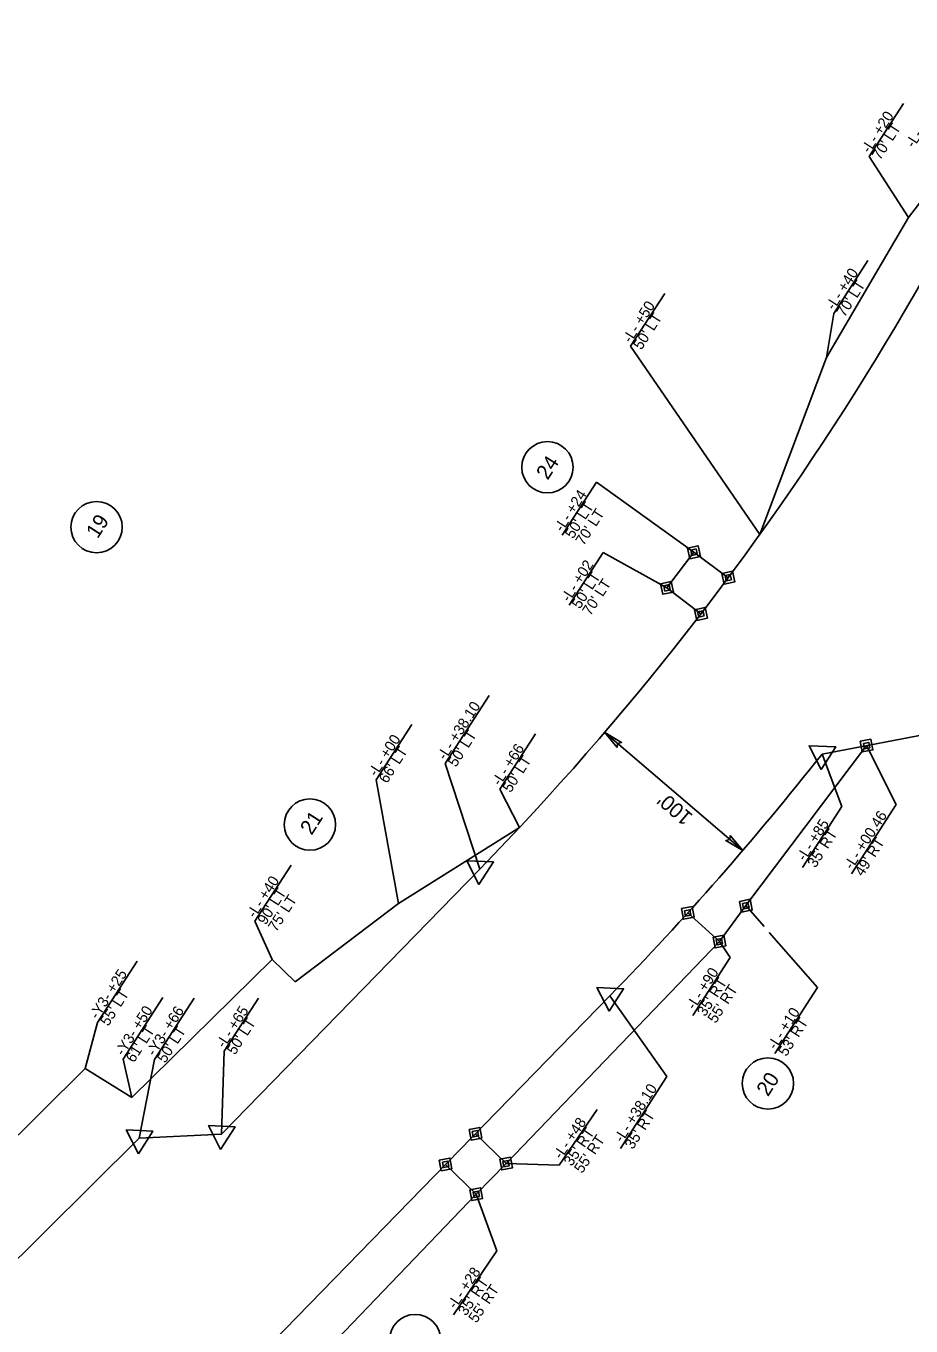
# Model space of a CAD drawing. Extents: x 1975689 to 1978251, y 778490 to 782347.
# Drawn here: x 1976742 to 1977156, y 779960 to 780568 of the extents above; entities that cross this region are included whole.
import ezdxf

# ---------------------------------------------------------------- set-up
doc = ezdxf.new("R2010")
doc.units = 0
for name, color, linetype in [('Prop Easement Aerial Utility', 7, 'Continuous'), ('Prop Easement Aerial Utility Station Offsets', 7, 'Continuous'), ('Prop Easement Construction', 7, 'Continuous'), ('Prop Easement Construction Station Offsets', 7, 'Continuous'), ('Prop Easement Permanent Drainage Utility', 7, 'Continuous'), ('Prop Easement Permanent Drainage Utility Station Offsets', 7, 'Continuous'), ('Prop Easement Permanent Utility', 7, 'Continuous'), ('Prop Parcel Number CELL', 7, 'Continuous'), ('Prop ROW Marker CELL', 7, 'Continuous'), ('Prop ROW Permanent Easement CELL', 7, 'Continuous'), ('Prop ROW RW Lines', 7, 'Continuous'), ('Prop ROW Station Offsets', 7, 'Continuous'), ('Prop ROW Text', 7, 'Continuous'), ('Prop Terminator CELL', 7, 'Continuous')]:
    doc.layers.add(name, color=color, linetype=linetype)

msp = doc.modelspace()

# ---------------------------------------------------------------- linework, layer by layer
at = {"layer": 'Prop Easement Aerial Utility'}
for p, q in [((1977041.51, 780305.06), (1977054.11, 780321.73)), ((1977054.11, 780321.73), (1977070.16, 780309.79)), ((1977041.51, 780305.06), (1977057.36, 780292.87))]:
    msp.add_line(p, q, dxfattribs=at)
at = {"layer": 'Prop Easement Aerial Utility Station Offsets'}
for p, q in [((1976992.52, 780329.72), (1977008.5, 780354.47)), ((1977054.11, 780321.73), (1977008.5, 780354.47)), ((1976995.68, 780296.89), (1977011.66, 780321.64)), ((1977041.51, 780305.06), (1977011.66, 780321.64))]:
    msp.add_line(p, q, dxfattribs=at)
at = {"layer": 'Prop Easement Construction'}
for p, q in [((1977154.47, 780478.39), (1977218.35, 780562.05)), ((1977116.16, 780412.76), (1977154.47, 780478.39)), ((1977084.94, 780330.04), (1977116.16, 780412.76)), ((1976915.88, 780157.37), (1976972.51, 780192.94)), ((1976867.56, 780120.68), (1976915.88, 780157.37)), ((1976791.21, 780066.63), (1976856.81, 780131.15)), ((1976856.81, 780131.15), (1976867.56, 780120.68)), ((1976698.3, 780009.8), (1976769.35, 780080.17)), ((1976769.35, 780080.17), (1976791.21, 780066.63))]:
    msp.add_line(p, q, dxfattribs=at)
at = {"layer": 'Prop Easement Construction Station Offsets'}
for p, q in [((1977136.12, 780506.87), (1977152.1, 780531.62)), ((1977154.47, 780478.39), (1977136.12, 780506.87)), ((1977119.52, 780433.44), (1977135.49, 780458.19)), ((1977024.45, 780418.08), (1977040.43, 780442.83)), ((1977116.16, 780412.76), (1977119.52, 780433.44)), ((1977024.45, 780418.08), (1977084.94, 780330.04)), ((1976905.47, 780215.23), (1976922.17, 780241.09)), ((1976963.31, 780210.92), (1976980, 780236.78)), ((1976915.88, 780157.37), (1976905.47, 780215.23)), ((1976972.51, 780192.94), (1976963.31, 780210.92)), ((1976848.71, 780149.05), (1976865.66, 780175.31)), ((1976856.81, 780131.15), (1976848.71, 780149.05)), ((1976775.11, 780101.69), (1976793.67, 780130.44)), ((1976787.12, 780084.57), (1976805.68, 780113.33)), ((1976769.35, 780080.17), (1976775.11, 780101.69)), ((1976791.21, 780066.63), (1976787.12, 780084.57))]:
    msp.add_line(p, q, dxfattribs=at)
at = {"layer": 'Prop Easement Permanent Drainage Utility'}
for p, q in [((1977078.38, 780156.36), (1977134.87, 780231.26)), ((1977066.05, 780139.53), (1977078.38, 780156.36)), ((1977051.22, 780152.94), (1977066.05, 780139.53)), ((1976966.24, 780035.68), (1976951.92, 780049.64)), ((1976952.28, 780021.36), (1976937.96, 780035.32)), ((1976952.28, 780021.36), (1976966.24, 780035.68))]:
    msp.add_line(p, q, dxfattribs=at)
at = {"layer": 'Prop Easement Permanent Drainage Utility Station Offsets'}
for p, q in [((1977148.64, 780203.7), (1977134.87, 780231.26)), ((1977127.77, 780171.24), (1977148.64, 780203.7)), ((1977087, 780146.53), (1977078.38, 780156.36)), ((1977111.88, 780118.12), (1977089.33, 780143.86)), ((1977071.04, 780132.15), (1977066.05, 780139.53)), ((1977053.54, 780104.89), (1977071.04, 780132.15)), ((1977092.02, 780087.19), (1977111.88, 780118.12)), ((1976991.15, 780034.98), (1977008.82, 780061.02)), ((1976991.15, 780034.98), (1976966.24, 780035.68)), ((1976961.98, 779994.83), (1976952.28, 780021.36)), ((1976941.71, 779964.95), (1976961.98, 779994.83))]:
    msp.add_line(p, q, dxfattribs=at)
at = {"layer": 'Prop Easement Permanent Utility'}
for p, q in [((1976966.24, 780035.68), (1977066.05, 780139.53)), ((1976859.48, 779924.69), (1976952.28, 780021.36))]:
    msp.add_line(p, q, dxfattribs=at)
at = {"layer": 'Prop Parcel Number CELL'}
for p, q in [((1976985.59, 780361.46), (1976985.59, 780361.46)), ((1976774.7, 780333.45), (1976774.7, 780333.45)), ((1976874.52, 780194.29), (1976874.52, 780194.29)), ((1977088.72, 780073.16), (1977088.72, 780073.16))]:
    msp.add_line(p, q, dxfattribs=at)
for centre in [(1976985.59, 780361.46), (1976774.7, 780333.45), (1976874.52, 780194.29), (1977088.72, 780073.16), (1976923.72, 779953.11)]:
    msp.add_circle(centre, 12, dxfattribs=at)
at = {"layer": 'Prop ROW Marker CELL'}
for p, q in [((1977054.11, 780321.73), (1977054.11, 780321.73)), ((1977070.16, 780309.79), (1977070.16, 780309.79)), ((1977041.51, 780305.06), (1977041.51, 780305.06)), ((1977057.36, 780292.87), (1977057.36, 780292.87)), ((1977134.87, 780231.26), (1977134.87, 780231.26)), ((1977114.05, 780227.31), (1977114.05, 780227.31)), ((1976953.93, 780173.49), (1976953.93, 780173.49)), ((1977078.38, 780156.36), (1977078.38, 780156.36)), ((1977051.22, 780152.94), (1977051.22, 780152.94)), ((1977066.05, 780139.53), (1977066.05, 780139.53)), ((1977014.81, 780114.17), (1977014.81, 780114.17)), ((1976794.65, 780047.52), (1976794.65, 780047.52)), ((1976833.12, 780049.52), (1976833.12, 780049.52)), ((1976951.92, 780049.64), (1976951.92, 780049.64)), ((1976937.96, 780035.32), (1976937.96, 780035.32)), ((1976966.24, 780035.68), (1976966.24, 780035.68)), ((1976952.28, 780021.36), (1976952.28, 780021.36))]:
    msp.add_line(p, q, dxfattribs=at)
for points in [[(1977113.69, 780220.11), (1977107.99, 780231.21), (1977120.45, 780230.62)], [(1976953.57, 780166.29), (1976947.88, 780177.4), (1976960.34, 780176.79)], [(1977014.45, 780106.97), (1977008.75, 780118.06), (1977021.21, 780117.48)], [(1976832.75, 780042.32), (1976827.07, 780053.43), (1976839.53, 780052.82)], [(1976794.29, 780040.32), (1976788.6, 780051.43), (1976801.07, 780050.82)]]:
    msp.add_lwpolyline(points, close=True, dxfattribs=at)
at = {"layer": 'Prop ROW Permanent Easement CELL'}
for points in [[(1977051.09, 780323.67), (1977056.06, 780324.76), (1977057.14, 780319.78), (1977052.17, 780318.7)], [(1977052.6, 780322.7), (1977055.09, 780323.24), (1977055.63, 780320.75), (1977053.14, 780320.21)], [(1977038.48, 780307.01), (1977043.45, 780308.09), (1977044.53, 780303.11), (1977039.56, 780302.03)], [(1977067.13, 780311.74), (1977072.11, 780312.82), (1977073.19, 780307.84), (1977068.21, 780306.76)], [(1977068.65, 780310.76), (1977071.13, 780311.3), (1977071.67, 780308.82), (1977069.19, 780308.27)], [(1977039.99, 780306.03), (1977042.48, 780306.57), (1977043.02, 780304.09), (1977040.53, 780303.54)], [(1977054.33, 780294.82), (1977059.31, 780295.9), (1977060.39, 780290.92), (1977055.42, 780289.84)], [(1977055.85, 780293.84), (1977058.34, 780294.38), (1977058.88, 780291.9), (1977056.39, 780291.35)], [(1977131.9, 780233.28), (1977136.9, 780234.24), (1977137.85, 780229.24), (1977132.85, 780228.28)], [(1977133.38, 780232.27), (1977135.88, 780232.75), (1977136.36, 780230.25), (1977133.86, 780229.77)], [(1977048.24, 780154.97), (1977053.24, 780155.92), (1977054.19, 780150.92), (1977049.19, 780149.97)], [(1977075.4, 780158.38), (1977080.4, 780159.34), (1977081.36, 780154.34), (1977076.36, 780153.38)], [(1977076.89, 780157.37), (1977079.39, 780157.85), (1977079.87, 780155.35), (1977077.37, 780154.87)], [(1977049.73, 780153.96), (1977052.23, 780154.43), (1977052.7, 780151.93), (1977050.2, 780151.45)], [(1977063.07, 780141.55), (1977068.07, 780142.51), (1977069.02, 780137.51), (1977064.03, 780136.55)], [(1977064.56, 780140.54), (1977067.06, 780141.02), (1977067.54, 780138.52), (1977065.04, 780138.04)], [(1976948.94, 780051.66), (1976953.94, 780052.62), (1976954.9, 780047.62), (1976949.9, 780046.66)], [(1976950.43, 780050.65), (1976952.93, 780051.13), (1976953.41, 780048.63), (1976950.91, 780048.15)], [(1976934.98, 780037.34), (1976939.98, 780038.29), (1976940.94, 780033.3), (1976935.94, 780032.34)], [(1976936.47, 780036.33), (1976938.97, 780036.81), (1976939.45, 780034.31), (1976936.95, 780033.83)], [(1976963.26, 780037.7), (1976968.26, 780038.66), (1976969.22, 780033.66), (1976964.22, 780032.7)], [(1976964.75, 780036.69), (1976967.25, 780037.17), (1976967.73, 780034.67), (1976965.23, 780034.19)], [(1976949.31, 780023.38), (1976954.31, 780024.34), (1976955.26, 780019.34), (1976950.26, 780018.38)], [(1976950.8, 780022.37), (1976953.3, 780022.85), (1976953.77, 780020.35), (1976951.27, 780019.87)]]:
    msp.add_lwpolyline(points, close=True, dxfattribs=at)
at = {"layer": 'Prop ROW RW Lines'}
for p, q in [((1977114.05, 780227.31), (1977181.17, 780240.04)), ((1976833.12, 780049.52), (1976953.93, 780173.49)), ((1976837.06, 779931.78), (1977014.81, 780114.17)), ((1976723.6, 779977.15), (1976794.65, 780047.52)), ((1976833.12, 780049.52), (1976794.65, 780047.52))]:
    msp.add_line(p, q, dxfattribs=at)
for radius, end in [(1350, 340.62647), (1435, 321.75126)]:
    msp.add_arc((1975987.1, 781115.69), radius, 315.73946, end, dxfattribs=at)
at = {"layer": 'Prop ROW Station Offsets'}
for p, q in [((1976937.75, 780222.89), (1976958.3, 780254.73)), ((1976953.93, 780173.49), (1976937.75, 780222.89)), ((1977123.31, 780202.79), (1977114.05, 780227.31)), ((1977104.94, 780174.23), (1977123.31, 780202.79)), ((1976801.75, 780084.4), (1976820.31, 780113.15)), ((1976834.38, 780088.22), (1976850.44, 780113.09)), ((1977041.39, 780076.45), (1977014.81, 780114.17)), ((1976794.65, 780047.52), (1976801.75, 780084.4)), ((1976833.12, 780049.52), (1976834.38, 780088.22)), ((1977019.74, 780042.74), (1977041.39, 780076.45))]:
    msp.add_line(p, q, dxfattribs=at)
at = {"layer": 'Prop ROW Text'}
msp.add_line((1977076.91, 780182.13), (1977012.36, 780237.43), dxfattribs=at)
at = {"layer": 'Prop Terminator CELL'}
for points in [[(1977018.18, 780230.4), (1977012.36, 780237.43), (1977020.27, 780232.76), (1977018.36, 780232.29)], [(1977071.08, 780189.16), (1977076.91, 780182.13), (1977069, 780186.8), (1977070.91, 780187.27)]]:
    msp.add_lwpolyline(points, close=True, dxfattribs=at)

# ---------------------------------------------------------------- texts
at = {"layer": 'Prop Easement Aerial Utility Station Offsets'}
for s, p in [('-L- +24', (1976992.62, 780330.89)), ("50' LT", (1976997.58, 780327.7)), ("70' LT", (1977002.53, 780324.5)), ('-L- +02', (1976995.79, 780298.06)), ("50' LT", (1977000.74, 780294.87)), ("70' LT", (1977005.69, 780291.67))]:
    msp.add_text(s, height=5, rotation=57.15853, dxfattribs=at).set_placement(p)
at = {"layer": 'Prop Easement Construction Station Offsets'}
for s, p in [('-L- +20', (1977136.23, 780508.04)), ('-L- +28', (1977156.9, 780510.57)), ("70' LT", (1977141.18, 780504.84)), ('-L- +40', (1977119.62, 780434.61)), ("70' LT", (1977124.57, 780431.41)), ('-L- +50', (1977024.56, 780419.25)), ("50' LT", (1977029.51, 780416.05)), ('-L- +00', (1976905.58, 780216.4)), ("66' LT", (1976910.53, 780213.21)), ('-L- +66', (1976963.41, 780212.09)), ("50' LT", (1976968.36, 780208.89)), ('-L- +40', (1976848.82, 780150.22)), ("90' LT", (1976853.77, 780147.02)), ("75' LT", (1976858.72, 780143.83)), ('-Y3- +25', (1976775.22, 780102.86)), ("55' LT", (1976780.17, 780099.66)), ('-Y3- +50', (1976787.23, 780085.74)), ("61' LT", (1976792.18, 780082.55))]:
    msp.add_text(s, height=5, rotation=57.15853, dxfattribs=at).set_placement(p)
at = {"layer": 'Prop Easement Permanent Drainage Utility Station Offsets'}
for s, rotation, p in [('-L- +00.46', 57.25497, (1977128.07, 780172.89)), ("49' RT", 57.25497, (1977133.02, 780169.71)), ('-L- +90', 57.28837, (1977054.37, 780107.32)), ("35' RT", 57.28837, (1977059.33, 780104.13)), ("55' RT", 57.28837, (1977064.29, 780100.95)), ('-L- +10', 57.28837, (1977092.35, 780088.64)), ("53' RT", 57.28837, (1977097.31, 780085.46)), ('-L- +48', 55.84408, (1976992.05, 780037.38)), ("35' RT", 55.84408, (1976996.93, 780034.07)), ("55' RT", 55.84408, (1977001.8, 780030.76)), ('-L- +28', 55.84408, (1976942.61, 779967.36)), ("35' RT", 55.84408, (1976947.48, 779964.05)), ("55' RT", 55.84408, (1976952.36, 779960.74))]:
    msp.add_text(s, height=5, rotation=rotation, dxfattribs=at).set_placement(p)
at = {"layer": 'Prop Parcel Number CELL'}
for s, p in [('24', (1976985.72, 780355.16)), ('19', (1976775.21, 780327.74)), ('21', (1976875.29, 780188.99)), ('20', (1977088.75, 780066.7))]:
    msp.add_text(s, height=7, rotation=57.28837, dxfattribs=at).set_placement(p)
at = {"layer": 'Prop ROW Station Offsets'}
for s, rotation, p in [('-L- +38.10', 57.15853, (1976937.85, 780224.06)), ("50' LT", 57.15853, (1976942.81, 780220.87)), ('-L- +85', 57.25497, (1977106, 780176.85)), ("35' RT", 57.25497, (1977110.95, 780173.67)), ('-Y3- +66', 57.15853, (1976801.85, 780085.57)), ('-L- +65', 57.15853, (1976834.49, 780089.39)), ("50' LT", 57.15853, (1976839.44, 780086.19)), ("50' LT", 57.15853, (1976806.8, 780082.37)), ('-L- +38.10', 57.28837, (1977020.57, 780045.16)), ("35' RT", 57.28837, (1977025.53, 780041.98))]:
    msp.add_text(s, height=5, rotation=rotation, dxfattribs=at).set_placement(p)
at = {"layer": 'Prop ROW Text'}
msp.add_text("100'", height=7, rotation=139.41601, dxfattribs=at).set_placement((1977054.04, 780198.57))

doc.saveas('drawing.dxf')
